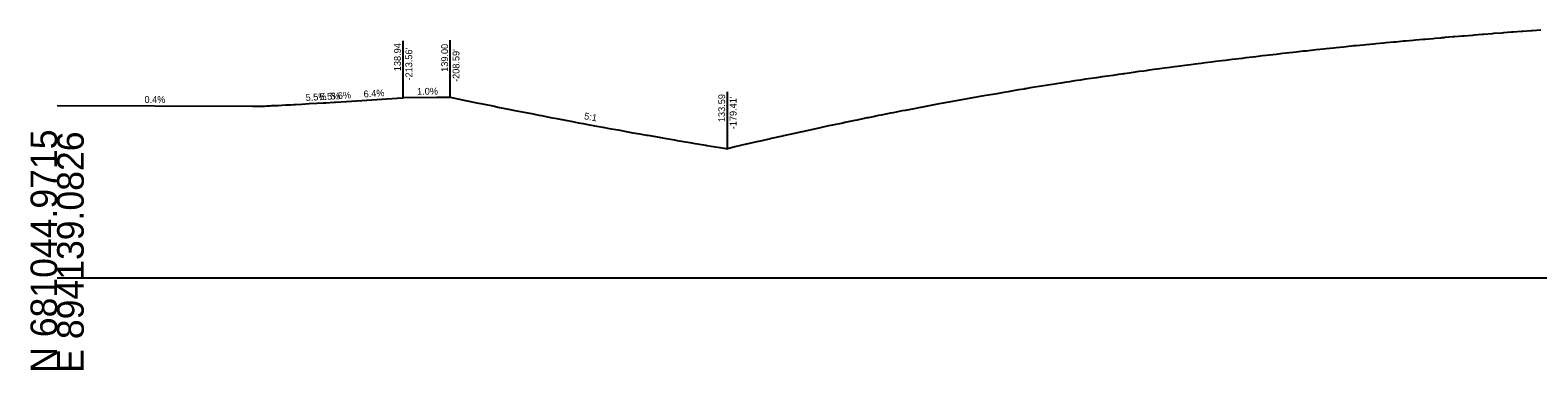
# Model space of a CAD drawing. Extents: x -26 to 4403, y -13 to 9578.
# Drawn here: x 1997.2 to 2155.9, y 990.3 to 1026.1 of the extents above; entities that cross this region are included whole.
import ezdxf

# ---------------------------------------------------------------- set-up
doc = ezdxf.new("R2010")
doc.units = 0
for name, color, linetype in [('Draft_XS_Grid', 7, 'Continuous'), ('DRAINAGE_SPUR_DIKES', 7, 'Continuous'), ('DTM_CORRIDOR', 7, 'Continuous'), ('DTM_X_GROUND', 7, 'Continuous'), ('SLOPE_STAKES_FILL', 7, 'Continuous'), ('XS_CELL', 7, 'Continuous'), ('XS_P_GROUND', 7, 'Continuous'), ('XS_P_TX_CLEARZONE', 7, 'Continuous'), ('XS_P_TX_FS_BS', 7, 'Continuous')]:
    doc.layers.add(name, color=color, linetype=linetype)

msp = doc.modelspace()

# ---------------------------------------------------------------- linework, layer by layer
at = {"layer": 'DTM_X_GROUND'}
msp.add_lwpolyline([(2000, 1018.14), (2020.6, 1018.06), (2020.71, 1018.06), (2020.84, 1018.06), (2021, 1018.06), (2021.19, 1018.06), (2021.49, 1018.06), (2021.58, 1018.06), (2021.83, 1018.07), (2022.07, 1018.09), (2022.33, 1018.1), (2022.44, 1018.11), (2022.62, 1018.12), (2022.94, 1018.13), (2023.1, 1018.14), (2023.29, 1018.15), (2023.68, 1018.17), (2024.1, 1018.2), (2024.58, 1018.22), (2024.93, 1018.24), (2025.12, 1018.25), (2025.78, 1018.29), (2026.53, 1018.33), (2027.36, 1018.38), (2028.02, 1018.41), (2028.29, 1018.43), (2029.17, 1018.48), (2029.33, 1018.49), (2030.48, 1018.56), (2036.33, 1018.94), (2036.44, 1018.94), (2036.44, 1018.94), (2036.44, 1018.94)], dxfattribs=at)
at = {"layer": 'XS_CELL'}
msp.add_line((2000, 1000), (2250, 1000), dxfattribs=at)
at = {"layer": 'XS_P_GROUND'}
for points in [[(2156.26, 1026.07), (2155.38, 1026), (2155.23, 1025.99), (2154.35, 1025.93), (2154.21, 1025.92), (2153.33, 1025.85), (2153.18, 1025.84), (2152.31, 1025.78), (2152.15, 1025.76), (2151.28, 1025.7), (2151.12, 1025.68), (2150.26, 1025.62), (2150.08, 1025.6), (2149.23, 1025.53), (2149.05, 1025.52), (2148.2, 1025.45), (2148.02, 1025.44), (2147.17, 1025.37), (2146.98, 1025.35), (2146.14, 1025.28), (2146.09, 1025.27), (2145.84, 1025.25), (2145.72, 1025.24), (2145.13, 1025.19), (2144.92, 1025.17), (2144.09, 1025.1), (2143.88, 1025.08), (2143.06, 1025.01), (2142.83, 1024.99), (2142.02, 1024.92), (2141.79, 1024.9), (2140.98, 1024.82), (2140.74, 1024.8), (2139.94, 1024.73), (2139.69, 1024.7), (2138.89, 1024.63), (2138.64, 1024.6), (2137.85, 1024.53), (2137.59, 1024.5), (2136.8, 1024.42), (2136.53, 1024.4), (2135.76, 1024.32), (2135.48, 1024.29), (2134.71, 1024.21), (2134.42, 1024.18), (2133.66, 1024.1), (2133.36, 1024.07), (2132.6, 1023.99), (2132.3, 1023.96), (2131.55, 1023.87), (2131.24, 1023.84), (2130.5, 1023.76), (2130.17, 1023.72), (2129.44, 1023.64), (2129.1, 1023.6), (2128.38, 1023.52), (2128.03, 1023.48), (2127.32, 1023.4), (2126.96, 1023.36), (2126.25, 1023.27), (2125.89, 1023.23), (2125.19, 1023.15), (2124.81, 1023.1), (2124.12, 1023.02), (2123.74, 1022.97), (2123.05, 1022.89), (2122.66, 1022.84), (2121.98, 1022.76), (2121.57, 1022.7), (2120.91, 1022.62), (2120.49, 1022.57), (2119.84, 1022.48), (2119.4, 1022.43), (2118.76, 1022.34), (2118.31, 1022.29), (2117.68, 1022.2), (2117.22, 1022.14), (2116.6, 1022.06), (2116.13, 1021.99), (2115.51, 1021.91), (2115.03, 1021.85), (2114.43, 1021.76), (2113.93, 1021.7), (2113.34, 1021.61), (2112.9, 1021.55), (2112.37, 1021.48), (2112.32, 1021.47), (2112.33, 1021.47), (2111.77, 1021.39), (2111.2, 1021.31), (2110.62, 1021.23), (2110.06, 1021.15), (2109.46, 1021.06), (2108.91, 1020.98), (2108.31, 1020.89), (2107.77, 1020.81), (2107.15, 1020.72), (2106.62, 1020.64), (2106.34, 1020.59), (2106.1, 1020.55), (2105.75, 1020.5), (2105.47, 1020.46), (2104.82, 1020.35), (2104.32, 1020.27), (2103.66, 1020.17), (2103.17, 1020.09), (2102.49, 1019.98), (2102.01, 1019.9), (2101.92, 1019.88), (2101.86, 1019.87), (2101.26, 1019.77), (2100.86, 1019.7), (2100.15, 1019.58), (2099.7, 1019.51), (2098.98, 1019.38), (2098.54, 1019.31), (2097.81, 1019.18), (2097.39, 1019.11), (2096.63, 1018.97), (2096.23, 1018.9), (2095.46, 1018.76), (2095.07, 1018.69), (2094.28, 1018.55), (2093.91, 1018.48), (2093.5, 1018.41), (2093.31, 1018.37), (2092.89, 1018.3), (2092.72, 1018.27), (2091.83, 1018.1), (2091.49, 1018.04), (2090.58, 1017.86), (2090.25, 1017.8), (2089.32, 1017.62), (2089.01, 1017.56), (2088.05, 1017.38), (2087.76, 1017.32), (2086.79, 1017.12), (2086.51, 1017.07), (2086.19, 1017), (2086.11, 1016.99), (2085.43, 1016.85), (2085.26, 1016.82), (2084.24, 1016.6), (2084, 1016.56), (2082.95, 1016.34), (2082.74, 1016.29), (2081.67, 1016.07), (2081.48, 1016.03), (2081.28, 1015.98), (2081.24, 1015.98), (2080.35, 1015.78), (2080.21, 1015.75), (2079.09, 1015.51), (2078.94, 1015.48), (2077.8, 1015.23), (2077.67, 1015.2), (2076.5, 1014.94), (2076.4, 1014.92), (2075.2, 1014.65), (2075.12, 1014.63), (2073.91, 1014.36), (2073.84, 1014.34), (2072.6, 1014.06), (2072.57, 1014.05), (2071.39, 1013.78), (2071.37, 1013.77), (2071.28, 1013.75), (2071.28, 1013.75), (2070.59, 1013.59)], [(2041.41, 1018.99), (2041.15, 1018.99), (2040.9, 1018.99), (2040.82, 1018.99), (2040.57, 1018.98), (2040.54, 1018.98), (2040.36, 1018.98), (2040.35, 1018.98), (2040, 1018.98), (2036.44, 1018.94)], [(2041.41, 1019), (2042.7, 1018.73), (2042.82, 1018.71), (2044.38, 1018.39), (2044.63, 1018.34), (2046.05, 1018.05), (2046.43, 1017.97), (2047.71, 1017.72), (2048.21, 1017.62), (2049.36, 1017.39), (2049.95, 1017.28), (2050.28, 1017.21), (2050.73, 1017.12), (2051.01, 1017.07), (2051.97, 1016.88), (2052.64, 1016.76), (2053.53, 1016.59), (2054.27, 1016.45), (2054.6, 1016.38), (2054.91, 1016.32), (2055.39, 1016.23), (2055.88, 1016.14), (2056.62, 1016.01), (2057.48, 1015.85), (2058.14, 1015.73), (2059.07, 1015.56), (2060.1, 1015.37), (2060.64, 1015.27), (2061.36, 1015.15), (2061.67, 1015.09), (2062.06, 1015.02), (2062.21, 1015), (2063.4, 1014.79), (2063.75, 1014.73), (2065.02, 1014.51), (2065.29, 1014.46), (2066.62, 1014.24), (2066.81, 1014.21), (2066.98, 1014.18), (2068.31, 1013.96), (2068.42, 1013.94), (2069.8, 1013.72), (2069.84, 1013.71), (2070.59, 1013.59)]]:
    msp.add_lwpolyline(points, dxfattribs=at)
at = {"layer": 'XS_P_TX_CLEARZONE'}
for p, q in [((2036.44, 1018.94), (2036.44, 1024.94)), ((2036.44, 1018.94), (2036.44, 1024.94)), ((2041.41, 1019), (2041.41, 1025)), ((2070.59, 1013.59), (2070.59, 1019.59))]:
    msp.add_line(p, q, dxfattribs=at)

# ---------------------------------------------------------------- texts
at = {"layer": 'Draft_XS_Grid'}
msp.add_text('-', height=0.0001, dxfattribs=at).set_placement((2000, 1000))
at = {"layer": 'DRAINAGE_SPUR_DIKES'}
msp.add_text('X', height=0.12, dxfattribs=at).set_placement((2041.37, 1018.94))
at = {"layer": 'DTM_CORRIDOR'}
for p in [(2036.4, 1018.88), (2070.55, 1013.53)]:
    msp.add_text('X', height=0.12, dxfattribs=at).set_placement(p)
at = {"layer": 'SLOPE_STAKES_FILL'}
msp.add_text('X', height=0.12, dxfattribs=at).set_placement((2036.4, 1018.88))
at = {"layer": 'XS_CELL'}
for s, p in [('N 681044.9715', (2000, 990)), ('E 894139.0826', (2002.8, 990))]:
    msp.add_text(s, height=2.8, rotation=90, dxfattribs=at).set_placement(p)
at = {"layer": 'XS_P_TX_CLEARZONE'}
for s, p in [('138.94', (2036.2, 1021.75)), ('138.94', (2036.2, 1021.75)), ("-213.56'", (2037.4, 1020.77)), ("-213.56'", (2037.4, 1020.77)), ('139.00', (2041.17, 1021.68)), ("-208.59'", (2042.37, 1020.62)), ('133.59', (2070.35, 1016.39)), ("-179.41'", (2071.55, 1015.64))]:
    msp.add_text(s, height=0.72, rotation=90, dxfattribs=at).set_placement(p)
at = {"layer": 'XS_P_TX_FS_BS'}
for s, rotation, p in [('5.5%', 3.1556, (2026.19, 1018.61)), ('5.5%', 3.1556, (2026.19, 1018.61)), ('5.5%', 3.1556, (2027.64, 1018.69)), ('5.5%', 3.1556, (2027.64, 1018.69)), ('6.6%', 3.7504, (2028.78, 1018.75)), ('6.6%', 3.7504, (2028.78, 1018.75)), ('6.4%', 3.6772, (2032.3, 1018.98)), ('6.4%', 3.6772, (2032.3, 1018.98)), ('1.0%', 0.5915, (2037.91, 1019.26)), ('0.4%', 359.7832, (2009.2, 1018.41)), ('0.4%', 359.7832, (2009.2, 1018.41)), ('5:1', 349.506, (2055.46, 1016.7))]:
    msp.add_text(s, height=0.72, rotation=rotation, dxfattribs=at).set_placement(p)

doc.saveas('drawing.dxf')
